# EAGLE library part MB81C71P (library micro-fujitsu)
MICROCONTROLLER/MEMORY DEVICE
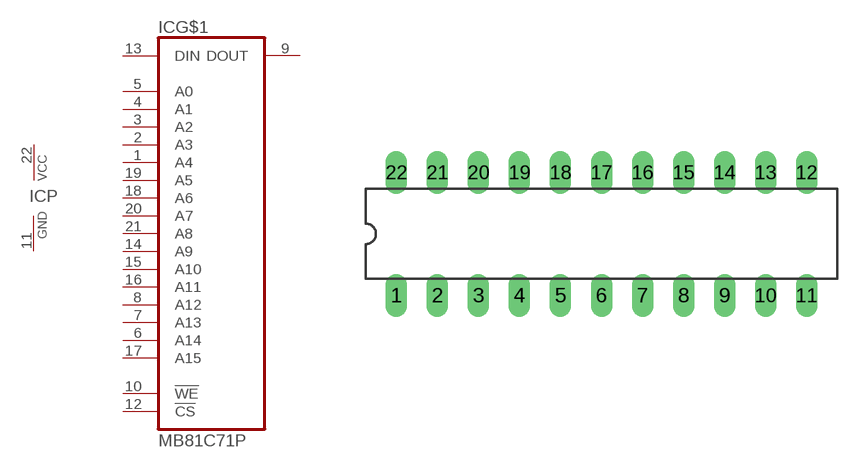
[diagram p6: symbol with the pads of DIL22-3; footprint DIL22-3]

Designator prefix IC; gates G$1=MB81C71 P=VCC-GND

## MB81C71P (OC_FARNELL: unknown; OC_NEWARK: unknown)  [DIL22-3]
1  G$1:A4  in
2  G$1:A3  in
3  G$1:A2  in
4  G$1:A1  in
5  G$1:A0  in
6  G$1:A14  in
7  G$1:A13  in
8  G$1:A12  in
9  G$1:DOUT  out
10  G$1:!WE  in
11  P:GND  pwr
12  G$1:!CS  in
13  G$1:DIN  in
14  G$1:A9  in
15  G$1:A10  in
16  G$1:A11  in
17  G$1:A15  in
18  G$1:A6  in
19  G$1:A5  in
20  G$1:A7  in
21  G$1:A8  in
22  P:VCC  pwr

## Footprint DIL22-3 (pad centres in mm)
Dual In Line Package 0.3 inch
drill 0.813 long: 1 -12.7,-3.81; 2 -10.16,-3.81; 3 -7.62,-3.81; 4 -5.08,-3.81; 5 -2.54,-3.81; 6 0,-3.81; 7 2.54,-3.81; 8 5.08,-3.81; 9 7.62,-3.81; 10 10.16,-3.81; 11 12.7,-3.81; 12 12.7,3.81; 13 10.16,3.81; 14 7.62,3.81; 15 5.08,3.81; 16 2.54,3.81; 17 0,3.81; 18 -2.54,3.81; 19 -5.08,3.81; 20 -7.62,3.81; 21 -10.16,3.81; 22 -12.7,3.81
